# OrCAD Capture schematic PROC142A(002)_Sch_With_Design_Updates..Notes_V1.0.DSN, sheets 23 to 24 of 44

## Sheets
23 22. CPSW RGMII_1 ETHERNET PHY: size C; title: CPSW RGMII_1 ETHERNET PHY
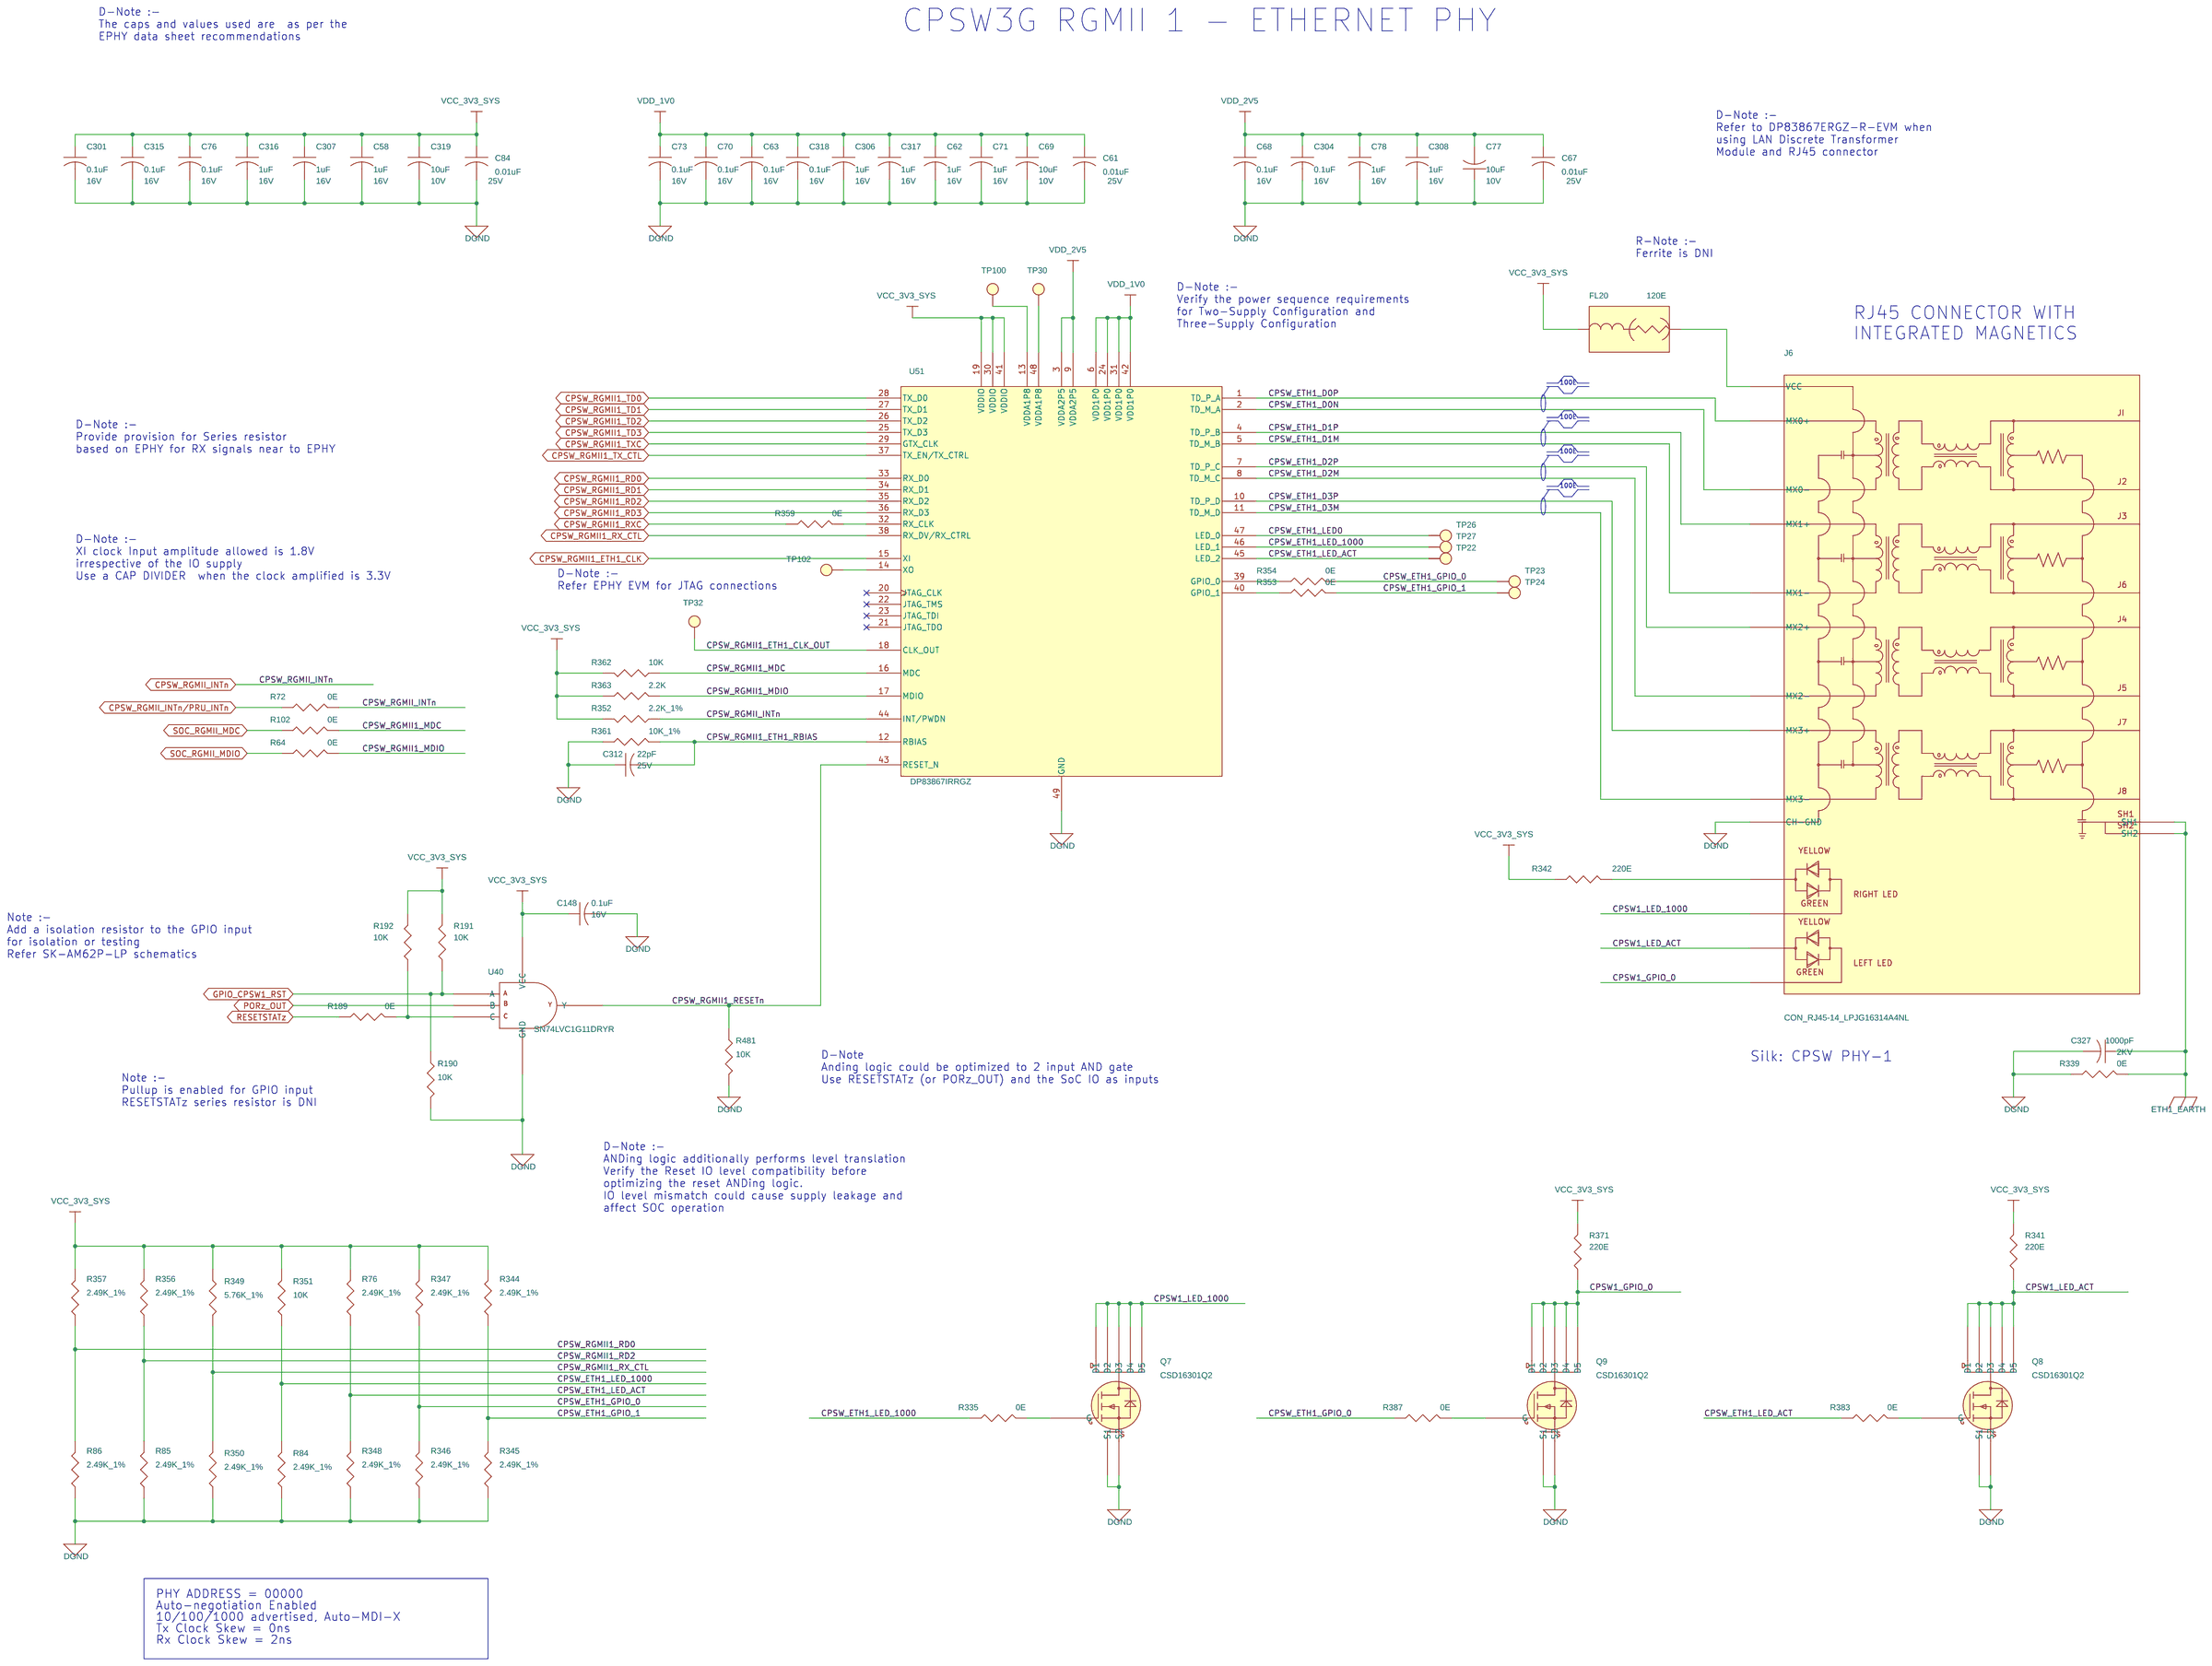
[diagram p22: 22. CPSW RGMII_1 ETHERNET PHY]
24 23. CPSW RGMII_2 ETHERNET PHY: size C; title: CPSW RGMII_2 ETHERNET PHY
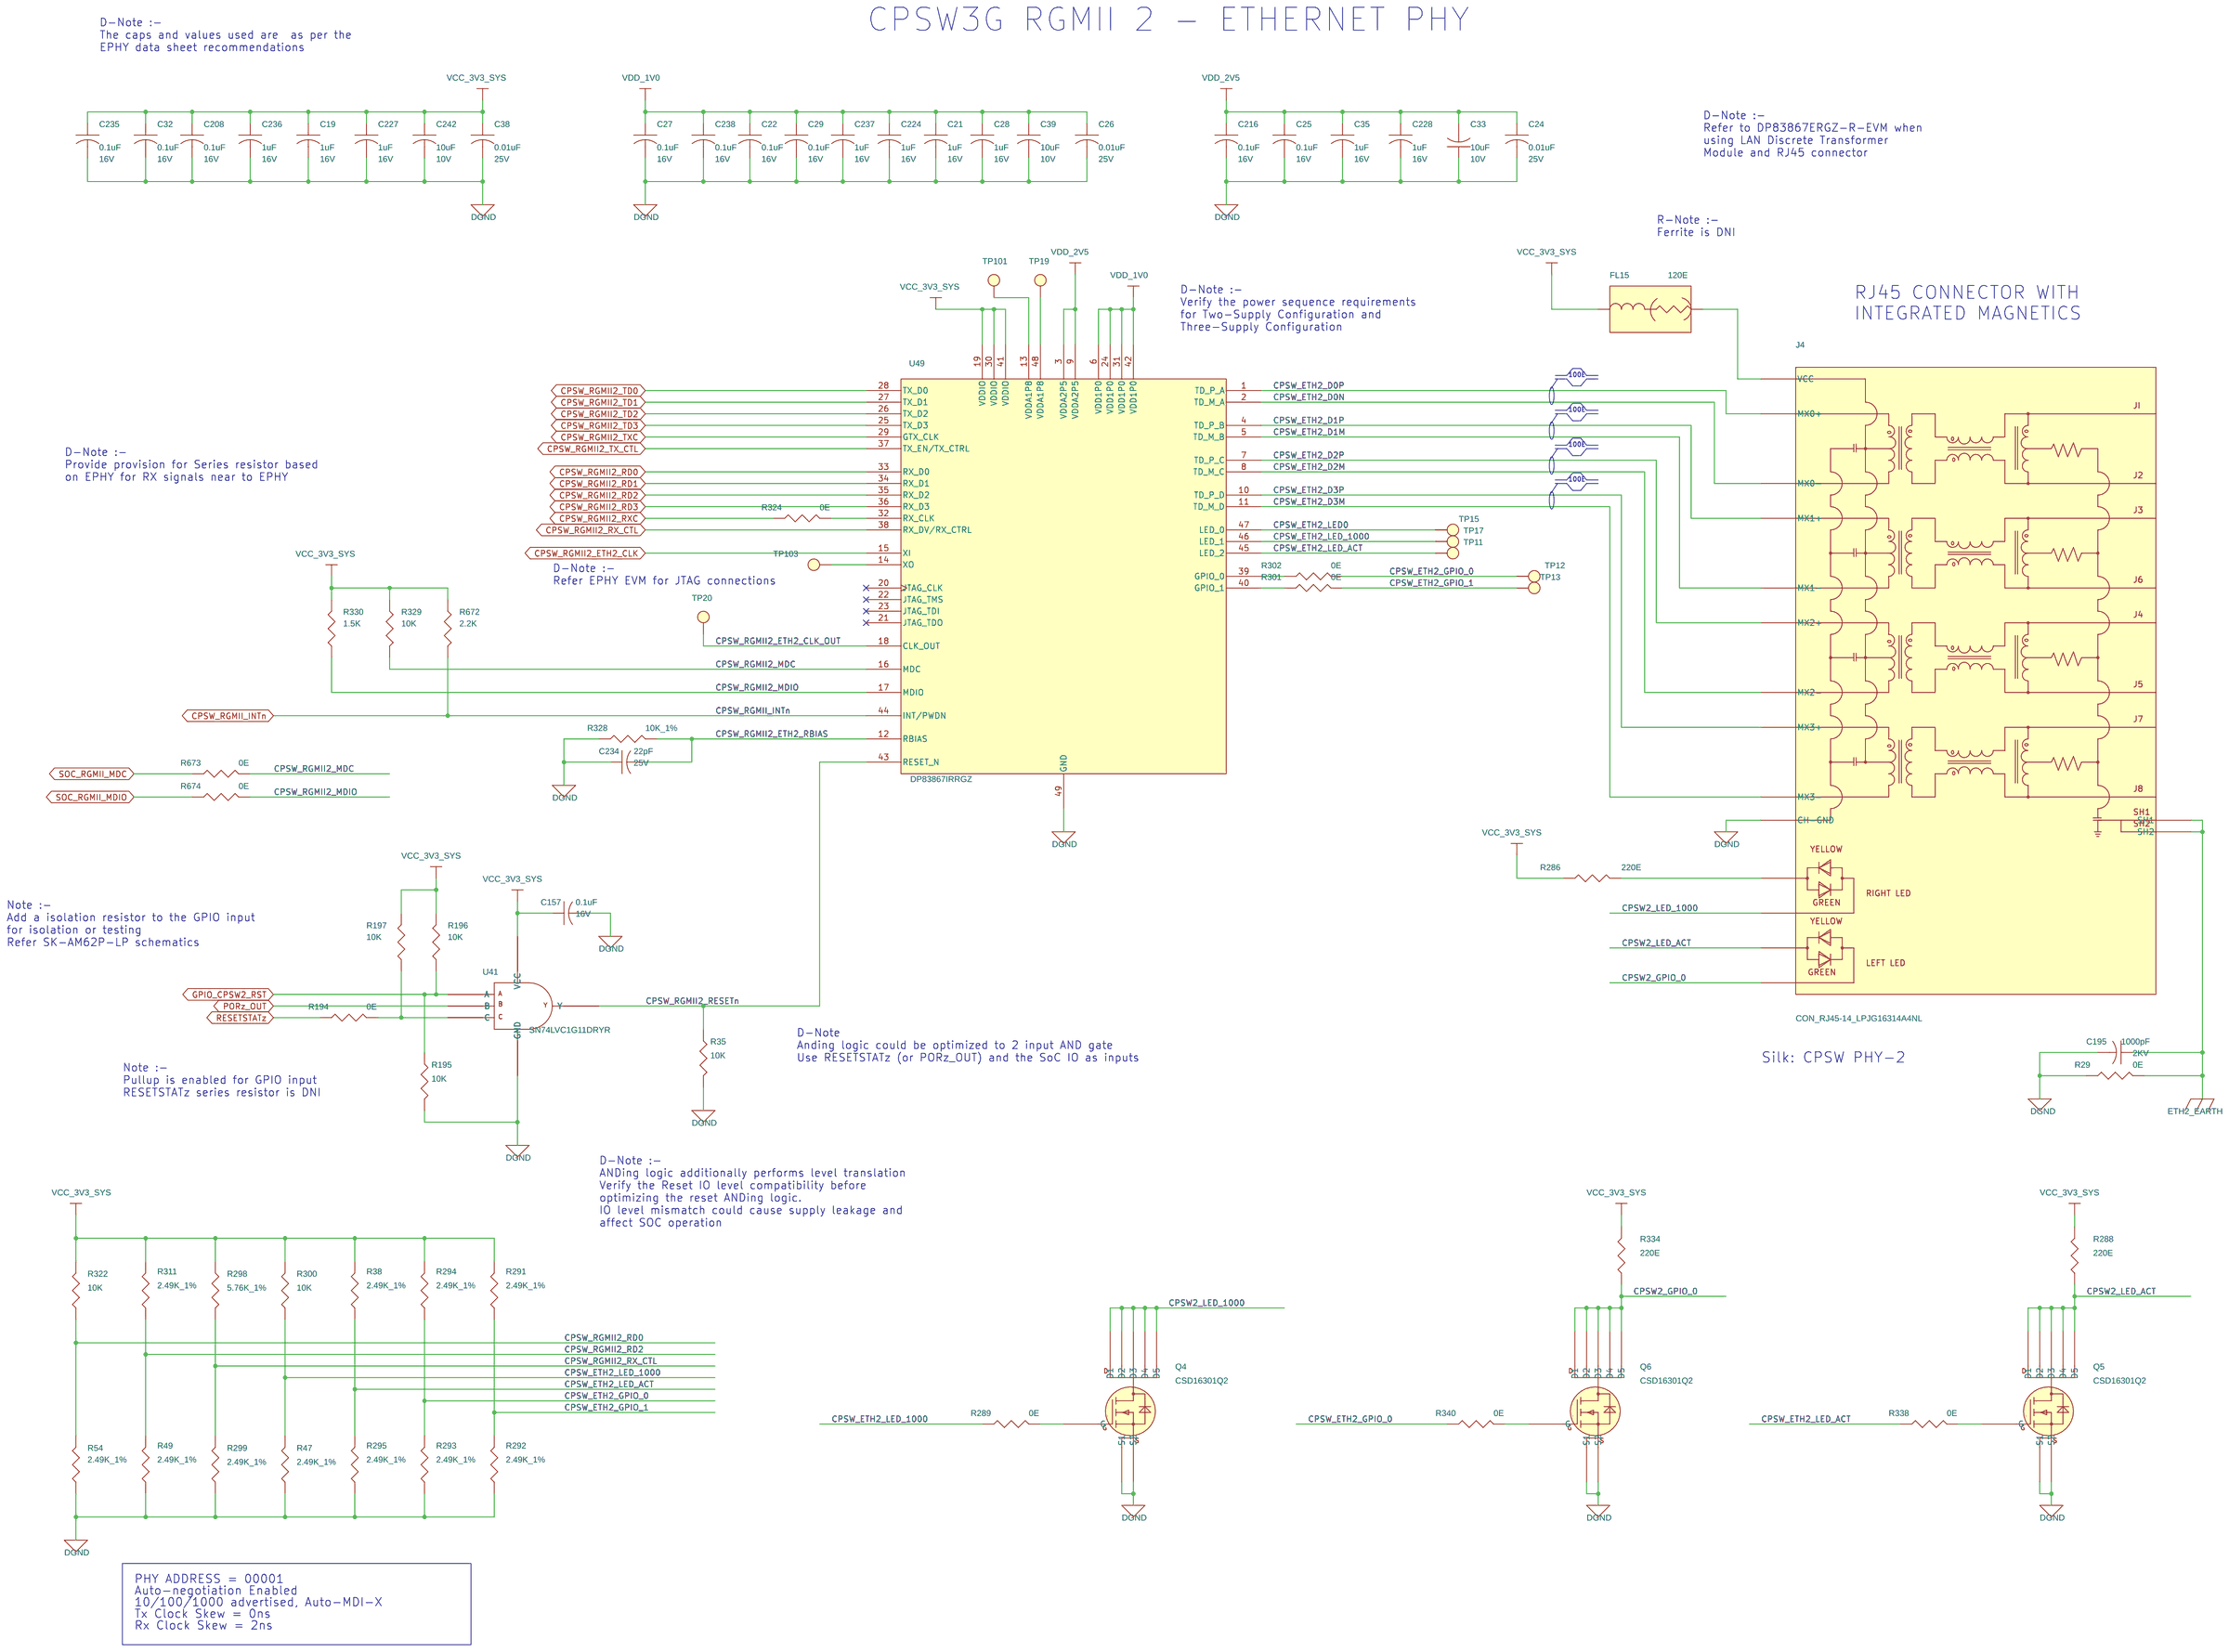
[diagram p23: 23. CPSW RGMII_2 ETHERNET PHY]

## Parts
sheet 22. CPSW RGMII_1 ETHERNET PHY
C58  1uF  [CAP0201_0-5]
C61  0.01uF  [CAP0201_0-5]
C62  1uF  [CAP0201_0-5]
C63  0.1uF  [CAP0201_0-5]
C67  0.01uF  [CAP0201_0-5]
C68  0.1uF  [CAP0201_0-5]
C69  10uF  [CAP0402_0-75]
C70  0.1uF  [CAP0201_0-5]
C71  1uF  [CAP0201_0-5]
C73  0.1uF  [CAP0201_0-5]
C76  0.1uF  [CAP0201_0-5]
C77  10uF  [CAP0402_0-75]
C78  1uF  [CAP0201_0-5]
C84  0.01uF  [CAP0201_0-5]
C148  0.1uF  [CAP0201_0-5]
C301  0.1uF  [CAP0201_0-5]
C304  0.1uF  [CAP0201_0-5]
C306  1uF  [CAP0201_0-5]
C307  1uF  [CAP0201_0-5]
C308  1uF  [CAP0201_0-5]
C312  22pF  [CAP0201_0-5]
C315  0.1uF  [CAP0201_0-5]
C316  1uF  [CAP0201_0-5]
C317  1uF  [CAP0201_0-5]
C318  0.1uF  [CAP0201_0-5]
C319  10uF  [CAP0402_0-75]
C327  1000pF  [CAP1206_1-75]
FL20  120E  [EMIFIL_BLM15P_0402]
J6  CON_RJ45-14_LPJG16314A4NL  [CON_RJ45-14_LPJG16314A4NL_S_R_T_13-6]
Q7  CSD16301Q2  [WSON6_CSD13202Q2_80X80_0-8]
Q8  CSD16301Q2  [WSON6_CSD13202Q2_80X80_0-8]
Q9  CSD16301Q2  [WSON6_CSD13202Q2_80X80_0-8]
R64  0E  [RES0402_0-5]
R72  0E  [RES0402_0-5]
R76  2.49K_1%  [RES0402_0-5]
R84  2.49K_1%  [RES0402_0-5]
R85  2.49K_1%  [RES0402_0-5]
R86  2.49K_1%  [RES0402_0-5]
R102  0E  [RES0402_0-5]
R189  0E  [RES0402_0-5]
R190  10K  [RES0201_0-5]
R191  10K  [RES0201_0-5]
R192  10K  [RES0201_0-5]
R335  0E  [RES0402_0-5]
R339  0E  [RES0603_0-75]
R341  220E  [RES0402_0-5]
R342  220E  [RES0402_0-5]
R344  2.49K_1%  [RES0402_0-5]
R345  2.49K_1%  [RES0402_0-5]
R346  2.49K_1%  [RES0402_0-5]
R347  2.49K_1%  [RES0402_0-5]
R348  2.49K_1%  [RES0402_0-5]
R349  5.76K_1%  [RES0402_0-5]
R350  2.49K_1%  [RES0402_0-5]
R351  10K  [RES0201_0-5]
R352  2.2K_1%  [RES0201_0-5]
R353  0E  [RES0201_0-5]
R354  0E  [RES0201_0-5]
R356  2.49K_1%  [RES0402_0-5]
R357  2.49K_1%  [RES0402_0-5]
R359  0E  [RES0402_0-5]
R361  10K_1%  [RES0201_0-5]
R362  10K  [RES0201_0-5]
R363  2.2K  [RES0201_0-5]
R371  220E  [RES0402_0-5]
R383  0E  [RES0402_0-5]
R387  0E  [RES0402_0-5]
R481  10K  [RES0201_0-5]
TP22  TP20_SMD  [TP20_SMD]
TP23  TP20_SMD  [TP20_SMD]
TP24  TP20_SMD  [TP20_SMD]
TP26  TP20_SMD  [TP20_SMD]
TP27  TP20_SMD  [TP20_SMD]
TP30  TP20_SMD  [TP20_SMD]
TP32  TP20_SMD  [TP20_SMD]
TP100  TP20_SMD  [TP20_SMD]
TP102  TP20_SMD  [TP20_SMD]
U40  SN74LVC1G11DRYR  [SON6_SN74LVC2G17_40X60_0-6]
U51  DP83867IRRGZ  [QFN48_19-68_280X280_1]
sheet 23. CPSW RGMII_2 ETHERNET PHY
C19  1uF  [CAP0201_0-5]
C21  1uF  [CAP0201_0-5]
C22  0.1uF  [CAP0201_0-5]
C24  0.01uF  [CAP0201_0-5]
C25  0.1uF  [CAP0201_0-5]
C26  0.01uF  [CAP0201_0-5]
C27  0.1uF  [CAP0201_0-5]
C28  1uF  [CAP0201_0-5]
C29  0.1uF  [CAP0201_0-5]
C32  0.1uF  [CAP0201_0-5]
C33  10uF  [CAP0402_0-75]
C35  1uF  [CAP0201_0-5]
C38  0.01uF  [CAP0201_0-5]
C39  10uF  [CAP0402_0-75]
C157  0.1uF  [CAP0201_0-5]
C195  1000pF  [CAP1206_1-75]
C208  0.1uF  [CAP0201_0-5]
C216  0.1uF  [CAP0201_0-5]
C224  1uF  [CAP0201_0-5]
C227  1uF  [CAP0201_0-5]
C228  1uF  [CAP0201_0-5]
C234  22pF  [CAP0201_0-5]
C235  0.1uF  [CAP0201_0-5]
C236  1uF  [CAP0201_0-5]
C237  1uF  [CAP0201_0-5]
C238  0.1uF  [CAP0201_0-5]
C242  10uF  [CAP0402_0-75]
FL15  120E  [EMIFIL_BLM15P_0402]
J4  CON_RJ45-14_LPJG16314A4NL  [CON_RJ45-14_LPJG16314A4NL_S_R_T_13-6]
Q4  CSD16301Q2  [WSON6_CSD13202Q2_80X80_0-8]
Q5  CSD16301Q2  [WSON6_CSD13202Q2_80X80_0-8]
Q6  CSD16301Q2  [WSON6_CSD13202Q2_80X80_0-8]
R29  0E  [RES0603_0-75]
R35  10K  [RES0201_0-5]
R38  2.49K_1%  [RES0402_0-5]
R47  2.49K_1%  [RES0402_0-5]
R49  2.49K_1%  [RES0402_0-5]
R54  2.49K_1%  [RES0402_0-5]
R194  0E  [RES0402_0-5]
R195  10K  [RES0201_0-5]
R196  10K  [RES0201_0-5]
R197  10K  [RES0201_0-5]
R286  220E  [RES0402_0-5]
R288  220E  [RES0402_0-5]
R289  0E  [RES0402_0-5]
R291  2.49K_1%  [RES0402_0-5]
R292  2.49K_1%  [RES0402_0-5]
R293  2.49K_1%  [RES0402_0-5]
R294  2.49K_1%  [RES0402_0-5]
R295  2.49K_1%  [RES0402_0-5]
R298  5.76K_1%  [RES0402_0-5]
R299  2.49K_1%  [RES0402_0-5]
R300  10K  [RES0201_0-5]
R301  0E  [RES0201_0-5]
R302  0E  [RES0201_0-5]
R311  2.49K_1%  [RES0402_0-5]
R322  10K  [RES0201_0-5]
R324  0E  [RES0402_0-5]
R328  10K_1%  [RES0201_0-5]
R329  10K  [RES0201_0-5]
R330  1.5K  [RES0201_0-5]
R334  220E  [RES0402_0-5]
R338  0E  [RES0402_0-5]
R340  0E  [RES0402_0-5]
R672  2.2K  [RES0201_0-5]
R673  0E  [RES0402_0-5]
R674  0E  [RES0402_0-5]
TP11  TP20_SMD  [TP20_SMD]
TP12  TP20_SMD  [TP20_SMD]
TP13  TP20_SMD  [TP20_SMD]
TP15  TP20_SMD  [TP20_SMD]
TP17  TP20_SMD  [TP20_SMD]
TP19  TP20_SMD  [TP20_SMD]
TP20  TP20_SMD  [TP20_SMD]
TP101  TP20_SMD  [TP20_SMD]
TP103  TP20_SMD  [TP20_SMD]
U41  SN74LVC1G11DRYR  [SON6_SN74LVC2G17_40X60_0-6]
U49  DP83867IRRGZ  [QFN48_19-68_280X280_1]

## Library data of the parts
C19 C21 C28 C35 C58 C62 C71 C78 C224 C227 C228 C236 C237 C306-C308 C316 C317 = CAP: CAP CERAMIC 1uF 16V 20% X5R 0201; Chkd/date: MANIRAJA/300520; Crtd /date: ALVY/260520; Custom_Duty: 15%; Customs_HS_Code: 85322990; Distributor_name: DIGIKEY; Distributor_part_number: 490-18654-1-ND; Footprint Path: Y:\MIS_DATABASE\Library\ALTIUM_TOOL\PCB_FOOTPRINTS\Altium_Footprint_Lib.PcbLib; Height: 0.39MM; Library Path: Y:\MIS_DATABASE\Library\ALTIUM_TOOL\SCHEMATICS_PARTS\MS_DISCRETE_Library.schlib; Mfr_name: MURATA; Mfr_part_number: GRM033R61C105ME15D; Mistral Part No: 120018090038-R; Package: 0201; Part_type: CAPACITORS\CERAMIC; Project: QCS610_NANOSOM; RoHS: RoHS; Temperature: -55°C+85°C; Tolerance: 20%; Voltage: 16V; Wattage: NA; Weight: 0.33mg; Datasheet: Y:\MIS_DATABASE\DATASHEETS\CAPACITORS\GRM033R61C105ME15.PDF
C24 C26 C38 C61 C67 C84 = CAP: CAP CERAMIC 0.01uF 25V 10% X5R 0201; Chkd/date: MANIRAJA/230118; Crtd /date: MANIRAJA/230118; Custom_Duty: 15%; Customs_HS_Code: 85322990; Distributor_name: DIGIKEY; Distributor_part_number: GRM033R61E103KA12J-ND; Footprint Path: Y:\MIS_DATABASE\Library\ALTIUM_TOOL\PCB_FOOTPRINTS\Altium_Footprint_Lib.PcbLib; Height: 0.33MM; Library Path: Y:\MIS_DATABASE\Library\ALTIUM_TOOL\SCHEMATICS_PARTS\MS_DISCRETE_Library.schlib; Mfr_name: MURATA; Mfr_part_number: GRM033R61E103KA12J; Mistral Part No: 120018010007-R; Package: 0201; Part_type: CAPACITORS\CERAMIC; Project: TI_MAXIE_CPB; RoHS: RoHS; Temperature: -55°C+85°C; Tolerance: 10%; Voltage: 25V; Wattage: NA; Weight: 0.33mg; Datasheet: Y:\MIS_DATABASE\DATASHEETS\CAPACITORS\GRM033R61E103KA12.PDF
C22 C25 C27 C29 C32 C63 C68 C70 C73 C76 C148 C157 C208 C216 C235 C238 C301 C304 C315 C318 = CAP: CAP CERAMIC 0.1uF 16V 10% X5R 0201; Alt_Mfr_name: YAGEO AMERICA; Alt_Mfr_part_number: CC0402KRX5R8BB104; Chkd/date: MANIRAJA/230118; Crtd /date: MANIRAJA/230118; Custom_Duty: 15%; Customs_HS_Code: 85322990; Distributor_name: DIGIKEY; Distributor_part_number: 490-14305-1-ND; Footprint Path: Y:\MIS_DATABASE\Library\ALTIUM_TOOL\PCB_FOOTPRINTS\Altium_Footprint_Lib.PcbLib; Height: 0.33MM; Library Path: Y:\MIS_DATABASE\Library\ALTIUM_TOOL\SCHEMATICS_PARTS\MS_DISCRETE_Library.schlib; Mfr_name: MURATA; Mfr_part_number: GRM033R61C104KE14D; Mistral Part No: 120009030072-R; Package: 0201; Part_type: CAPACITORS\CERAMIC; Project: TI_MAXIE_CPB; RoHS: RoHS; Temperature: -55°C+85°C; Tolerance: 10%; Voltage: 16V; Wattage: NA; Weight: 0.33mg; Datasheet: Y:\MIS_DATABASE\DATASHEETS\CAPACITORS\GRM033R61C104KE14.PDF
C33 C39 C69 C77 C242 C319 = CAP: CAP CERAMIC 10uF 10V 20% X5R 0402; Chkd/date: MANIRAJA/300520; Crtd /date: ALVY/260520; Custom_Duty: 15%; Customs_HS_Code: 85322990; Distributor_name: DIGIKEY; Distributor_part_number: 490-GRM155R61A106ME11DTR-ND; Footprint Path: Y:\MIS_DATABASE\Library\ALTIUM_TOOL\PCB_FOOTPRINTS\Altium_Footprint_Lib.PcbLib; Height: 0.55MM; Library Path: Y:\MIS_DATABASE\Library\ALTIUM_TOOL\SCHEMATICS_PARTS\MS_DISCRETE_Library.schlib; Mfr_name: MURATA; Mfr_part_number: GRM155R61A106ME11D; Mistral Part No: 120013110019-R; Package: 0402; Part_type: CAPACITORS\CERAMIC; Project: QCS610_NANOSOM; RoHS: RoHS; Temperature: -55°C+85°C; Tolerance: 20%; Voltage: 10V; Wattage: NA; Weight: 3.1mg; Datasheet: Y:\MIS_DATABASE\DATASHEETS\CAPACITORS\MURATA-GXX-SER_NOV17.PDF
C234 C312 = CAP: CAP CERAMIC 22pF 25V 1% C0G(NP0) 0201; Chkd/date: MANIRAJA/270721; Crtd /date: ALVY/260721; Custom_Duty: 15%; Customs_HS_Code: 85322990; Distributor_name: DIGIKEY; Distributor_part_number: 490-14545-1-ND; Footprint Path: Y:\MIS_DATABASE\Library\ALTIUM_TOOL\PCB_FOOTPRINTS\Altium_Footprint_Lib.PcbLib; Height: 0.33MM; Library Path: Y:\MIS_DATABASE\Library\ALTIUM_TOOL\SCHEMATICS_PARTS\MS_DISCRETE_Library.schlib; Mfr_name: MURATA; Mfr_part_number: GRM0335C1E220FA01D; Mistral Part No: 120021070019-R; Package: 0201; Part_type: CAPACITORS\CERAMIC; Project: TI_AM335x SK_BRD; RoHS: RoHS; Temperature: -55°C+125°C; Tolerance: 1%; Voltage: 25V; Wattage: NA; Weight: 0.33mg; Datasheet: Y:\MIS_DATABASE\DATASHEETS\CAPACITORS\GRM0335C1E220FA01.PDF
C195 C327 = CAP: CAP CERAMIC 1000pF 2KV 10% X7R 1206; Chkd/date: SHREESHAIL/291106; Crtd /date: MAZHAR/281106; Custom_Duty: 15%; Customs_HS_Code: 85322990; Distributor_name: DIGIKEY; Distributor_part_number: 478-2956-1-ND; Footprint Path: Y:\MIS_DATABASE\Library\ALTIUM_TOOL\PCB_FOOTPRINTS\Altium_Footprint_Lib.PcbLib; Height: 1.52MM; Library Path: Y:\MIS_DATABASE\Library\ALTIUM_TOOL\SCHEMATICS_PARTS\MS_DISCRETE_Library.schlib; Mfr_name: AVX CORPORATION; Mfr_part_number: 1206GC102KAT1A; Mistral Part No: 120015080006-R; Package: 1206; Part_type: CAPACITORS\CERAMIC; Project: ADR1B; RoHS: RoHS; Temperature: -55°C+125°C; Tolerance: 10%; Voltage: 2KV; Wattage: NA; Weight: 16.2mg; Datasheet: Y:\MIS_DATABASE\DATASHEETS\CAPACITORS\AVX_HV-MLC.PDF
FL15 FL20 = EMIFILTER_IND: FERRITE CHIP 120E 2A 0402; Chkd/date: NAVEED/241114; Crtd /date: USMAN/170613; Custom_Duty: 24%; Customs_HS_Code: 85369090; Distributor_name: MOUSER; Distributor_part_number: 81-BLM15PX121SN1D; Height: 0.55MM; Mfr_name: MURATA; Mfr_part_number: BLM15PX121SN1D; Mistral Part No: 130013060022-R; Package: 0402; Part_type: FILTER; Project: GEN_3-8; RoHS: RoHS; Temperature: -55°C+125°C; Tolerance: 25%; Voltage: NA; Wattage: NA; Weight: NA; Datasheet: Y:\MIS_DATABASE\DATASHEETS\DISCRETES\INDUCTORS\BLM15X.PDF
J4 J6 = CON_RJ45-14_LPJG16314A4NL: CON RJ-45 FEMALE 14POS RT TH; Chkd/date: VASANTHA/150714; Crtd /date: BALACHANDAR/120614; Custom_Duty: 24%; Customs_HS_Code: 85369090; Distributor_name: NA; Distributor_part_number: NA; Footprint Path: Y:\MIS_DATABASE\Library\ALTIUM_TOOL\PCB_FOOTPRINTS\Altium_Footprint_Lib.PcbLib; Height: 13.60MM; Library Path: Y:\MIS_DATABASE\Library\ALTIUM_TOOL\SCHEMATICS_PARTS\MS_CONNECTOR_Library.schlib; Mfr_name: LINK-PP; Mfr_part_number: LPJG16314A4NL; Mistral Part No: 150014060029-R; Package: THRU-HOLE; Part_type: CONNECTOR\JACK; Project: AEGIS; RoHS: RoHS; Temperature: -0°C+70°C; Tolerance: NA; Voltage: NA; Wattage: NA; Weight: NA; Datasheet: Y:\MIS_DATABASE\DATASHEETS\CONNECTORS\LPJG16314A4NL.PDF
Q4-Q9 = MOSFET_CSD17313Q2: IC MOSFET N-CHANNEL NEXFET 25V WSON6; Chkd/date: ALVY/071220; Crtd /date: MANIRAJA/071220; Custom_Duty: 15%; Customs_HS_Code: 85423100; Distributor_name: DIGIKEY; Distributor_part_number: 296-25260-1-ND; Footprint Path: Y:\MIS_DATABASE\Library\ALTIUM_TOOL\PCB_FOOTPRINTS\Altium_Footprint_Lib.PcbLib; Height: 0.80MM; Library Path: Y:\MIS_DATABASE\Library\ALTIUM_TOOL\SCHEMATICS_PARTS\MS_MOSFET_Library.schlib; Mfr_name: TEXAS INSTRUMENTS; Mistral Part No: 142020120008-R; Package: WSON6; Part_type: ICS\POWER\MOSFET; Project: TI_AM243x LP EVM; RoHS: RoHS; Temperature: -55°C+150°C; Tolerance: NA; Voltage: NA; Wattage: NA; Weight: 8.7mg; Datasheet: Y:\MIS_DATABASE\DATASHEETS\ICS\POWER\CSD16301Q2.PDF
R64 R72 R102 R189 R194 R289 R335 R338 R340 R383 R387 R673 R674 = RESISTOR: RES 0E 1/16W JUMPER 0402; Chkd/date: VASANTHA/201216; Crtd /date: MUDDU/190810; Custom_Duty: 15%; Customs_HS_Code: 85332119; Distributor_name: DIGIKEY; Distributor_part_number: 541-0.0JCT-ND; Footprint Path: Y:\MIS_DATABASE\Library\ALTIUM_TOOL\PCB_FOOTPRINTS\Altium_Footprint_Lib.PcbLib; Height: 0.40MM; Library Path: Y:\MIS_DATABASE\Library\ALTIUM_TOOL\SCHEMATICS_PARTS\MS_DISCRETE_Library.schlib; Mfr_name: VISHAY; Mfr_part_number: CRCW04020000Z0ED; Mistral Part No: 110010080019-R; Package: 0402; Part_type: RESISTORS\FIXED; Project: PB_BUGBASE; RoHS: RoHS; Temperature: -55°C+155°C; Tolerance: NA; Voltage: NA; Wattage: 1/16W; Weight: 0.65mg; Datasheet: Y:\MIS_DATABASE\DATASHEETS\RESISTORS\CRCW0603.PDF
R38 R47 R49 R54 R76 R84-R86 R291-R295 R299 R311 R344-R348 R350 R356 R357 = RESISTOR: RES 2.49K 1/16W 1% 0402; Chkd/date: VASANTHA/270516; Crtd /date: VASANTHA/270516; Custom_Duty: 15%; Customs_HS_Code: 85332119; Distributor_name: DIGIKEY; Distributor_part_number: 311-2.49KLRCT-ND; Footprint Path: Y:\MIS_DATABASE\Library\ALTIUM_TOOL\PCB_FOOTPRINTS\Altium_Footprint_Lib.PcbLib; Height: 0.40MM; Library Path: Y:\MIS_DATABASE\Library\ALTIUM_TOOL\SCHEMATICS_PARTS\MS_DISCRETE_Library.schlib; Mfr_name: YAGEO AMERICA; Mfr_part_number: RC0402FR-072K49L; Mistral Part No: 110016050020-R; Package: 0402; Part_type: RESISTORS\FIXED; Project: TMDXCSKCC; RoHS: RoHS; Temperature: -55°C+155°C; Tolerance: 1%; Voltage: NA; Wattage: 1/16W; Weight: 0.65mg; Datasheet: Y:\MIS_DATABASE\DATASHEETS\RESISTORS\RCXXXXL-SER_MAR18.PDF
R35 R190-R192 R195-R197 R300 R322 R329 R351 R362 R481 = RESISTOR: RES 10K 1/20W 5% 0201; Chkd/date: MANIRAJA/050517; Crtd /date: MANIRAJA/050517; Custom_Duty: 15%; Customs_HS_Code: 85332119; Distributor_name: DIGIKEY; Distributor_part_number: 311-10KNCT-ND; Footprint Path: Y:\MIS_DATABASE\Library\ALTIUM_TOOL\PCB_FOOTPRINTS\Altium_Footprint_Lib.PcbLib; Height: 0.26MM; Library Path: Y:\MIS_DATABASE\Library\ALTIUM_TOOL\SCHEMATICS_PARTS\MS_DISCRETE_Library.schlib; Mfr_name: YAGEO AMERICA; Mfr_part_number: RC0201JR-0710KL; Mistral Part No: 110010070051-R; Package: 0201; Part_type: RESISTORS\FIXED; Project: GOLDEN-I LITE; RoHS: RoHS; Temperature: -55°C+125°C; Tolerance: 5%; Voltage: NA; Wattage: 1/20W; Weight: 0.17mg; Datasheet: Y:\MIS_DATABASE\DATASHEETS\RESISTORS\RCXXXXL-SER_MAR18.PDF
R29 R339 = RESISTOR: RES 0E 1/10W 5% 0603; Chkd/date: MANIRAJA/051217; Crtd /date: BAVISH/180211; Custom_Duty: 15%; Customs_HS_Code: 85332119; Distributor_name: DIGIKEY; Distributor_part_number: 311-0.0GRCT-ND; Footprint Path: Y:\MIS_DATABASE\Library\ALTIUM_TOOL\PCB_FOOTPRINTS\Altium_Footprint_Lib.PcbLib; Height: 0.55MM; Library Path: Y:\MIS_DATABASE\Library\ALTIUM_TOOL\SCHEMATICS_PARTS\MS_DISCRETE_Library.schlib; Manufacturer: YAGEO AMERICA; Mfr_name: PANASONIC-ECG; Mfr_part_number: RC0603JR-070RL; Mistral Part No: 110011020013-R; Package: 0603; Part_type: RESISTORS\FIXED; Project: KENNEL; RoHS: RoHS; Temperature: -55°C+155°C; Tolerance: 5%; Voltage: NA; Wattage: 1/10W; Weight: 2mg; Datasheet: Y:\MIS_DATABASE\DATASHEETS\RESISTORS\RCXXXXL-SER_MAR18.PDF
R286 R288 R334 R341 R342 R371 = RESISTOR: RES 220E 1/10W 5% 0402; Chkd/date: VASANTHA/291216; Crtd /date: GEETHA/260406; Custom_Duty: 15%; Customs_HS_Code: 85332119; Distributor_name: DIGIKEY; Distributor_part_number: P220JCT-ND; Footprint Path: Y:\MIS_DATABASE\Library\ALTIUM_TOOL\PCB_FOOTPRINTS\Altium_Footprint_Lib.PcbLib; Height: 0.40MM; Library Path: Y:\MIS_DATABASE\Library\ALTIUM_TOOL\SCHEMATICS_PARTS\MS_DISCRETE_Library.schlib; Mfr_name: PANASONIC-ECG; Mfr_part_number: ERJ-2GEJ221X; Mistral Part No: 110009030506-R; Package: 0402; Part_type: RESISTORS\FIXED; Project: RED EYE; RoHS: RoHS; Temperature: -55°C+155°C; Tolerance: 5%; Voltage: NA; Wattage: 1/10W; Weight: 0.8mg; Datasheet: Y:\MIS_DATABASE\DATASHEETS\RESISTORS\PAN-ERJSER_NOV17.PDF
R298 R349 = RESISTOR: RES 5.76K 1/10W 1% 0402; Chkd/date: MAZHAR/150709; Crtd /date: USMAN/220808; Custom_Duty: 15%; Customs_HS_Code: 85332119; Distributor_name: DIGIKEY; Distributor_part_number: P5.76KLCT-ND; Footprint Path: Y:\MIS_DATABASE\Library\ALTIUM_TOOL\PCB_FOOTPRINTS\Altium_Footprint_Lib.PcbLib; Height: 0.40MM; Library Path: Y:\MIS_DATABASE\Library\ALTIUM_TOOL\SCHEMATICS_PARTS\MS_DISCRETE_Library.schlib; Mfr_name: PANASONIC-ECG; Mfr_part_number: ERJ-2RKF5761X; Mistral Part No: 110009030945-R; Package: 0402; Part_type: RESISTORS\FIXED; Project: CPB; RoHS: RoHS; Temperature: -55°C+155°C; Tolerance: 1%; Voltage: NA; Wattage: 1/10W; Weight: 0.8mg; Datasheet: Y:\MIS_DATABASE\DATASHEETS\RESISTORS\PAN-ERJSER_NOV17.PDF
R352 = RESISTOR: RES 2.2K 1/20W 1% 0201; Chkd/date: VASANTHA/270117; Crtd /date: MANIRAJA/270117; Custom_Duty: 15%; Customs_HS_Code: 85332119; Distributor_name: DIGIKEY; Distributor_part_number: YAG2572CT-ND; Footprint Path: Y:\MIS_DATABASE\Library\ALTIUM_TOOL\PCB_FOOTPRINTS\Altium_Footprint_Lib.PcbLib; Height: 0.26MM; Library Path: Y:\MIS_DATABASE\Library\ALTIUM_TOOL\SCHEMATICS_PARTS\MS_DISCRETE_Library.schlib; Manufacturer: YAGEO AMERICA; Mfr_name: PANASONIC-ECG; Mfr_part_number: RC0201FR-072K2L; Mistral Part No: 110017010016-R; Package: 0201; Part_type: RESISTORS\FIXED; Project: GOLDEN-I LITE; RoHS: RoHS; Temperature: -55°C+125°C; Tolerance: 1%; Voltage: NA; Wattage: 1/20W; Weight: 0.17mg; Datasheet: Y:\MIS_DATABASE\DATASHEETS\RESISTORS\RCXXXXL-SER_MAR18.PDF
R301 R302 R353 R354 = RESISTOR: RES 0E 1/20W 5% 0201; Chkd/date: NAVEED/301214; Crtd /date: MUDDU/120710; Custom_Duty: 15%; Customs_HS_Code: 85332119; Distributor_name: DIGIKEY; Distributor_part_number: 311-0.0NCT-ND; Footprint Path: Y:\MIS_DATABASE\Library\ALTIUM_TOOL\PCB_FOOTPRINTS\Altium_Footprint_Lib.PcbLib; Height: 0.26MM; Library Path: Y:\MIS_DATABASE\Library\ALTIUM_TOOL\SCHEMATICS_PARTS\MS_DISCRETE_Library.schlib; Mfr_name: YAGEO AMERICA; Mfr_part_number: RC0201JR-070RL; Mistral Part No: 110010070067-R; Package: 0201; Part_type: RESISTORS\FIXED; Project: PB_BUGBASE; RoHS: RoHS; Temperature: -55°C+125°C; Tolerance: 5%; Voltage: NA; Wattage: 1/20W; Weight: 0.17mg; Datasheet: Y:\MIS_DATABASE\DATASHEETS\RESISTORS\RCXXXXL-SER_MAR18.PDF
R324 R359 = RESISTOR: RES 0E 1/16W JUMPER 0402; Chkd/date: VASANTHA/201216; Crtd /date: MUDDU/190810; Custom_Duty: 15%; Customs_HS_Code: 85332119; Distributor_name: DIGIKEY; Distributor_part_number: 541-0.0JCT-ND; Footprint Path: Y:\MIS_DATABASE\Library\ALTIUM_TOOL\PCB_FOOTPRINTS\Altium_Footprint_Lib.PcbLib; Height: 0.40MM; Library Path: Y:\MIS_DATABASE\Library\ALTIUM_TOOL\SCHEMATICS_PARTS\MS_DISCRETE_Library.schlib; Mfr_name: VISHAY; Mfr_part_number: CRCW04020000Z0ED; Mistral Part No: 110010080019-R; Package: 0402; Part_type: RESISTORS\FIXED; Project: PB_BUGBASE; RoHS: RoHS; SIGNAL_MODEL: RESISTOR_RES0402_0-5_0E_0E; Temperature: -55°C+155°C; Tolerance: NA; Voltage: NA; Wattage: 1/16W; Weight: 0.65mg; Datasheet: Y:\MIS_DATABASE\DATASHEETS\RESISTORS\CRCW0603.PDF
R328 R361 = RESISTOR: RES 10K 1/20W 1% 0201; Chkd/date: VASANTHA/270117; Crtd /date: MANIRAJA/270117; Custom_Duty: 15%; Customs_HS_Code: 85332119; Distributor_name: DIGIKEY; Distributor_part_number: 311-10.0KMCT-ND; Footprint Path: Y:\MIS_DATABASE\Library\ALTIUM_TOOL\PCB_FOOTPRINTS\Altium_Footprint_Lib.PcbLib; Height: 0.26MM; Library Path: Y:\MIS_DATABASE\Library\ALTIUM_TOOL\SCHEMATICS_PARTS\MS_DISCRETE_Library.schlib; Manufacturer: YAGEO AMERICA; Mfr_name: YAGEO AMERICA; Mfr_part_number: RC0201FR-0710KL; Mistral Part No: 110011040018-R; Package: 0201; Part_type: RESISTORS\FIXED; Project: GOLDEN-I LITE; RoHS: RoHS; Temperature: -55°C+125°C; Tolerance: 1%; Voltage: NA; Wattage: 1/20W; Weight: 0.17mg; Datasheet: Y:\MIS_DATABASE\DATASHEETS\RESISTORS\RCXXXXL-SER_MAR18.PDF
R363 R672 = RESISTOR: RES 2.2K 1/20W 5% 0201; Chkd/date: VASANTHA/010117; Crtd /date: MAZHAR/010605; Custom_Duty: 15%; Customs_HS_Code: 85332119; Distributor_name: DIGIKEY; Distributor_part_number: P2.2KAGCT-ND; Footprint Path: Y:\MIS_DATABASE\Library\ALTIUM_TOOL\PCB_FOOTPRINTS\Altium_Footprint_Lib.PcbLib; Height: 0.26MM; Library Path: Y:\MIS_DATABASE\Library\ALTIUM_TOOL\SCHEMATICS_PARTS\MS_DISCRETE_Library.schlib; Mfr_name: PANASONIC-ECG; Mfr_part_number: ERJ-1GEJ222C; Mistral Part No: 110009030427-R; Package: 0201; Part_type: RESISTORS\FIXED; Project: G4SLIM; RoHS: RoHS; Temperature: -55°C+125°C; Tolerance: 5%; Voltage: NA; Wattage: 1/20W; Weight: 0.15mg; Datasheet: Y:\MIS_DATABASE\DATASHEETS\RESISTORS\PAN-ERJXGE-FEB06.PDF
TP11-TP13 TP15 TP17 TP19 TP20 TP22-TP24 TP26 TP27 TP30 TP32 TP100-TP103 = TESTPOINT: TESTPOINT CIR 20 SMD; Chkd/date: SHREESHAIL/171006; Crtd /date: MAZHAR/171006; Custom_Duty: NA; Customs_HS_Code: NA; Distributor_name: NA; Distributor_part_number: NA; Footprint Path: Y:\MIS_DATABASE\Library\ALTIUM_TOOL\PCB_FOOTPRINTS\Altium_Footprint_Lib.PcbLib; Height: NA; Library Path: Y:\MIS_DATABASE\Library\ALTIUM_TOOL\SCHEMATICS_PARTS\MS_DISCRETE_Library.schlib; MECHANICAL 3D STEP FILE: NA; Mfr_name: LOCAL; Mistral Part No: NA; Package: SMD; Project: BT MODULE_CSRBC04; RoHS: NA; Temperature: NA; Tolerance: NA; Voltage: NA; Wattage: NA; Weight: NA; Datasheet: NA
U40 U41 = SN74LVC1G11DCKR_SC70-6: IC SINGLE 3-INPUT POSITIVE-AND GATE SON6; Chkd/date: MANIRAJA/270121; Crtd /date: ALVY/270121; Custom_Duty: 15%; Customs_HS_Code: 85423100; Distributor_name: DIGIKEY; Distributor_part_number: 296-30120-1-ND; Footprint Path: Y:\MIS_DATABASE\Library\ALTIUM_TOOL\PCB_FOOTPRINTS\Altium_Footprint_Lib.PcbLib; Height: 0.60MM; Library Path: Y:\MIS_DATABASE\Library\ALTIUM_TOOL\SCHEMATICS_PARTS\MS_GATE_Library.schlib; Mfr_name: TEXAS INSTRUMENTS; Mistral Part No: 141021010013-R; Package: SON6; Part_type: ICS\DIGITAL\GATES; Project: AM64X_SKEVM; RoHS: RoHS; Temperature: -40°C+125°C; Tolerance: NA; Voltage: NA; Wattage: NA; Weight: 33mg; Datasheet: Y:\MIS_DATABASE\DATASHEETS\ICS\DIGITAL\GATES\SN74LVC1G_NOV16.PDF
U49 U51 = DP83867IRRGZ_VQFN48: IC HIGH IMMUNITY 10/100/1000 Mb/s ETHERNET PHY LAYER TRANSCEIVER VQFN48; Chkd/date: MANIRAJA/110817; Crtd /date: MANIRAJA/110817; Custom_Duty: 15%; Customs_HS_Code: 85423100; Distributor_name: DIGIKEY; Distributor_part_number: DP83867IRRGZT-ND; Height: 1.00MM; Mfr_name: TEXAS INSTRUMENTS; Mistral Part No: 143017080002-R; Package: VQFN48; Part_type: ICS\TELECOM\TRANSCEIVER; Project: TI_SVB_CONTROLLER CARD; RoHS: RoHS; Temperature: -40°C+85°C; Tolerance: NA; Voltage: NA; Wattage: NA; Weight: NA; Datasheet: Y:\MIS_DATABASE\DATASHEETS\ICS\DIGITAL\BUSTRANSCEIVER\DP83867I.PDF
R330 = RESISTOR: RES 1.5K 1/20W 5% 0201; Chkd/date: MAZHAR/130208; Crtd /date: USMAN/130208; Custom_Duty: 15%; Customs_HS_Code: 85332119; Distributor_name: DIGIKEY; Distributor_part_number: P1.5KAGCT-ND; Footprint Path: Y:\MIS_DATABASE\Library\ALTIUM_TOOL\PCB_FOOTPRINTS\Altium_Footprint_Lib.PcbLib; Height: 0.26MM; Library Path: Y:\MIS_DATABASE\Library\ALTIUM_TOOL\SCHEMATICS_PARTS\MS_DISCRETE_Library.schlib; Manufacturer: PANASONIC-ECG; Mfr_name: PANASONIC-ECG; Mfr_part_number: ERJ-1GEJ152C; Mistral Part No: 110010070057-R; Package: 0201; Part_type: RESISTORS\FIXED; Project: SMART VIEW_IP CAMERA; RoHS: RoHS; Temperature: -55°C+125°C; Tolerance: 5%; Voltage: NA; Wattage: 1/20W; Weight: 0.15mg; Datasheet: Y:\MIS_DATABASE\DATASHEETS\RESISTORS\PAN-ERJXGE-FEB06.PDF

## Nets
DGND: C19.2 C21.2 C22.2 C24.2 C25.2 C26.2 C27.2 C28.2 C29.2 C32.2 C33.1 C35.2 C38.2 C39.2 C58.2 C61.2 C62.2 C63.2 C67.2 C68.2 C69.2 C70.2 C71.2 C73.2 C76.2 C77.1 C78.2 C84.2 C148.2 C157.2 C195.2 C208.2 C216.2 C224.2 C227.2 C228.2 C234.1 C235.2 C236.2 C237.2 C238.2 C242.2 C301.2 C304.2 C306.2 C307.2 C308.2 C312.1 C315.2 C316.2 C317.2 C318.2 C319.2 C327.2 J4.1(CH-GND) J6.1(CH-GND) Q4.4(S1) Q4.7(S2) Q5.4(S1) Q5.7(S2) Q6.4(S1) Q6.7(S2) Q7.4(S1) Q7.7(S2) Q8.4(S1) Q8.7(S2) Q9.4(S1) Q9.7(S2) R29.2 R35.2 R47.1 R49.1 R54.1 R84.1 R85.1 R86.1 R190.2 R195.2 R292.1 R293.1 R295.1 R299.1 R328.2 R339.2 R345.1 R346.1 R348.1 R350.1 R361.2 R481.2 U40.2(GND) U41.2(GND) U49.49(GND) U51.49(GND) ; also on sheet 1 10 11 12 13 14 15 16 17 18 19 20 21 22 25 26 27 28 29 30 31 32 33 34 35 36 37 38 39 40 41 42 43
VCC_3V3_SYS: C19.1 C32.1 C38.1 C58.1 C76.1 C84.1 C148.1 C157.1 C208.1 C227.1 C235.1 C236.1 C242.1 C301.1 C307.1 C315.1 C316.1 C319.1 FL15.1 FL20.1 R38.2 R76.2 R191.2 R192.2 R196.2 R197.2 R286.1 R288.2 R291.2 R294.2 R298.1 R300.2 R311.2 R322.2 R329.1 R330.2 R334.2 R341.2 R342.1 R344.2 R347.2 R349.1 R351.2 R352.2 R356.2 R357.2 R362.2 R363.1 R371.2 R672.1 U40.5(VCC) U41.5(VCC) U49.19(VDDIO) U49.30(VDDIO) U49.41(VDDIO) U51.19(VDDIO) U51.30(VDDIO) U51.41(VDDIO) ; also on sheet 10 12 13 14 18 19 20 22 25 26 27 29 30 31 32 33 34 35 36 37 38 39 40 41 42 43
VDD_1V0: C21.1 C22.1 C26.1 C27.1 C28.1 C29.1 C39.1 C61.1 C62.1 C63.1 C69.1 C70.1 C71.1 C73.1 C224.1 C237.1 C238.1 C306.1 C317.1 C318.1 U49.6(VDD1P0) U49.24(VDD1P0) U49.31(VDD1P0) U49.42(VDD1P0) U51.6(VDD1P0) U51.24(VDD1P0) U51.31(VDD1P0) U51.42(VDD1P0) ; also on sheet 12
VDD_2V5: C24.1 C25.1 C33.2 C35.1 C67.1 C68.1 C77.2 C78.1 C216.1 C228.1 C304.1 C308.1 U49.3(VDDA2P5) U49.9(VDDA2P5) U51.3(VDDA2P5) U51.9(VDDA2P5) ; also on sheet 13 17
CPSW1_GPIO_0: J6.14 Q9.1(D1) Q9.2(D2) Q9.5(D3) Q9.6(D4) Q9.8(D5) R371.1
CPSW1_LED_1000: J6.12 Q7.1(D1) Q7.2(D2) Q7.5(D3) Q7.6(D4) Q7.8(D5)
CPSW1_LED_ACT: J6.13 Q8.1(D1) Q8.2(D2) Q8.5(D3) Q8.6(D4) Q8.8(D5) R341.1
CPSW2_GPIO_0: J4.14 Q6.1(D1) Q6.2(D2) Q6.5(D3) Q6.6(D4) Q6.8(D5) R334.1
CPSW2_LED_1000: J4.12 Q4.1(D1) Q4.2(D2) Q4.5(D3) Q4.6(D4) Q4.8(D5)
CPSW2_LED_ACT: J4.13 Q5.1(D1) Q5.2(D2) Q5.5(D3) Q5.6(D4) Q5.8(D5) R288.1
CPSW_ETH1_D0N: J6.10(MX0-) U51.2(TD_M_A)
CPSW_ETH1_D0P: J6.9(MX0+) U51.1(TD_P_A)
CPSW_ETH1_D1M: J6.8(MX1-) U51.5(TD_M_B)
CPSW_ETH1_D1P: J6.7(MX1+) U51.4(TD_P_B)
CPSW_ETH1_D2M: J6.6(MX2-) U51.8(TD_M_C)
CPSW_ETH1_D2P: J6.5(MX2+) U51.7(TD_P_C)
CPSW_ETH1_D3M: J6.4(MX3-) U51.11(TD_M_D)
CPSW_ETH1_D3P: J6.3(MX3+) U51.10(TD_P_D)
CPSW_ETH1_GPIO_0: R346.2 R347.1 R354.1 R387.1 TP23.1(TP)
CPSW_ETH1_GPIO_1: R344.1 R345.2 R353.1 TP24.1(TP)
CPSW_ETH1_LED0: TP26.1(TP) U51.47(LED_0)
CPSW_ETH1_LED_1000: R84.2 R335.1 R351.1 TP27.1(TP) U51.46(LED_1)
CPSW_ETH1_LED_ACT: R76.1 R348.2 R383.1 TP22.1(TP) U51.45(LED_2)
CPSW_ETH2_D0N: J4.10(MX0-) U49.2(TD_M_A)
CPSW_ETH2_D0P: J4.9(MX0+) U49.1(TD_P_A)
CPSW_ETH2_D1M: J4.8(MX1-) U49.5(TD_M_B)
CPSW_ETH2_D1P: J4.7(MX1+) U49.4(TD_P_B)
CPSW_ETH2_D2M: J4.6(MX2-) U49.8(TD_M_C)
CPSW_ETH2_D2P: J4.5(MX2+) U49.7(TD_P_C)
CPSW_ETH2_D3M: J4.4(MX3-) U49.11(TD_M_D)
CPSW_ETH2_D3P: J4.3(MX3+) U49.10(TD_P_D)
CPSW_ETH2_GPIO_0: R293.2 R294.1 R302.1 R340.1 TP12.1(TP)
CPSW_ETH2_GPIO_1: R291.1 R292.2 R301.1 TP13.1(TP)
CPSW_ETH2_LED0: TP15.1(TP) U49.47(LED_0)
CPSW_ETH2_LED_1000: R47.2 R289.1 R300.1 TP17.1(TP) U49.46(LED_1)
CPSW_ETH2_LED_ACT: R38.1 R295.2 R338.1 TP11.1(TP) U49.45(LED_2)
CPSW_RGMII1_ETH1_CLK: U51.15(XI) ; also on sheet 25
CPSW_RGMII1_ETH1_CLK_OUT: TP32.1(TP) U51.18(CLK_OUT)
CPSW_RGMII1_ETH1_RBIAS: C312.2 R361.1 U51.12(RBIAS)
CPSW_RGMII1_MDC: R102.2 R362.1 U51.16(MDC)
CPSW_RGMII1_MDIO: R64.2 R363.2 U51.17(MDIO)
CPSW_RGMII1_RD0: R86.2 R357.1 U51.33(RX_D0) ; also on sheet 25
CPSW_RGMII1_RD1: U51.34(RX_D1) ; also on sheet 25
CPSW_RGMII1_RD2: R85.2 R356.1 U51.35(RX_D2) ; also on sheet 25
CPSW_RGMII1_RD3: U51.36(RX_D3) ; also on sheet 25
CPSW_RGMII1_RESETn: R481.1 U40.4(Y) U51.43(RESET_N)
CPSW_RGMII1_RX_CTL: R349.2 R350.2 U51.38(RX_DV/RX_CTRL) ; also on sheet 25
CPSW_RGMII1_RXC: R359.1 ; also on sheet 25
CPSW_RGMII1_TD0: U51.28(TX_D0) ; also on sheet 25
CPSW_RGMII1_TD1: U51.27(TX_D1) ; also on sheet 25
CPSW_RGMII1_TD2: U51.26(TX_D2) ; also on sheet 25
CPSW_RGMII1_TD3: U51.25(TX_D3) ; also on sheet 25
CPSW_RGMII1_TX_CTL: U51.37(TX_EN/TX_CTRL) ; also on sheet 25
CPSW_RGMII1_TXC: U51.29(GTX_CLK) ; also on sheet 25
CPSW_RGMII2_ETH2_CLK: U49.15(XI) ; also on sheet 25
CPSW_RGMII2_ETH2_CLK_OUT: TP20.1(TP) U49.18(CLK_OUT)
CPSW_RGMII2_ETH2_RBIAS: C234.2 R328.1 U49.12(RBIAS)
CPSW_RGMII2_MDC: R329.2 R673.2 U49.16(MDC)
CPSW_RGMII2_MDIO: R330.1 R674.2 U49.17(MDIO)
CPSW_RGMII2_RD0: R54.2 R322.1 U49.33(RX_D0) ; also on sheet 25
CPSW_RGMII2_RD1: U49.34(RX_D1) ; also on sheet 25
CPSW_RGMII2_RD2: R49.2 R311.1 U49.35(RX_D2) ; also on sheet 25
CPSW_RGMII2_RD3: U49.36(RX_D3) ; also on sheet 25
CPSW_RGMII2_RESETn: R35.1 U41.4(Y) U49.43(RESET_N)
CPSW_RGMII2_RX_CTL: R298.2 R299.2 U49.38(RX_DV/RX_CTRL) ; also on sheet 25
CPSW_RGMII2_RXC: R324.1 ; also on sheet 25
CPSW_RGMII2_TD0: U49.28(TX_D0) ; also on sheet 25
CPSW_RGMII2_TD1: U49.27(TX_D1) ; also on sheet 25
CPSW_RGMII2_TD2: U49.26(TX_D2) ; also on sheet 25
CPSW_RGMII2_TD3: U49.25(TX_D3) ; also on sheet 25
CPSW_RGMII2_TX_CTL: U49.37(TX_EN/TX_CTRL) ; also on sheet 25
CPSW_RGMII2_TXC: U49.29(GTX_CLK) ; also on sheet 25
CPSW_RGMII_INTn: R72.2 R352.1 R672.2 U49.44(INT/PWDN) U51.44(INT/PWDN)
CPSW_RGMII_INTn/PRU_INTn: R72.1 ; also on sheet 32 42
ETH1_EARTH: C327.1 J6.15(SH1) J6.16(SH2) R339.1
ETH2_EARTH: C195.1 J4.15(SH1) J4.16(SH2) R29.1
GPIO_CPSW1_RST: R190.1 R191.1 U40.1(A) ; also on sheet 39
GPIO_CPSW2_RST: R195.1 R196.1 U41.1(A) ; also on sheet 39
PORz_OUT: U40.3(B) U41.3(B) ; also on sheet 20 27 42
RESETSTATz: R189.1 R194.1 ; also on sheet 13 19 20 21 27 32 33 37 39 40 41 42
SOC_RGMII_MDC: R102.1 R673.1 ; also on sheet 32
SOC_RGMII_MDIO: R64.1 R674.1 ; also on sheet 32
N16800246: FL15.2 J4.2(VCC)
N17110597: TP100.1(TP) U51.13(VDDA1P8)
N17133547: FL20.2 J6.2(VCC)
N17137240: J6.11 R342.2
N17149186: TP101.1(TP) U49.13(VDDA1P8)
N17149287: J4.11 R286.2
N17167245: R359.2 U51.32(RX_CLK)
N17167691: R324.2 U49.32(RX_CLK)
N17269599: R189.2 R192.1 U40.6(C)
N17434691: TP19.1(TP) U49.48(VDDA1P8)
N17473283: R194.2 R197.1 U41.6(C)
N17653582: Q7.3(G) R335.2
N17654451: Q4.3(G) R289.2
N17796705: Q8.3(G) R383.2
N17796716: Q9.3(G) R387.2
N17799775: Q6.3(G) R340.2
N17800599: Q5.3(G) R338.2
N18576337: R354.2 U51.39(GPIO_0)
N18576340: R353.2 U51.40(GPIO_1)
N18576730: R302.2 U49.39(GPIO_0)
N18576733: R301.2 U49.40(GPIO_1)
N20273833: TP30.1(TP) U51.48(VDDA1P8)
N20274021: TP102.1(TP) U51.14(XO)
N20274420: TP103.1(TP) U49.14(XO)

Not connected (* = marked no-connect by the designer): U49 20(JTAG_CLK)* 21(JTAG_TDO)* 22(JTAG_TMS)* 23(JTAG_TDI)*; U51 20(JTAG_CLK)* 21(JTAG_TDO)* 22(JTAG_TMS)* 23(JTAG_TDI)*

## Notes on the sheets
sheet 23
- D-Note :-
  The caps and values used are  as per the
  EPHY data sheet recommendations
- CPSW3G RGMII 1 - ETHERNET PHY
- D-Note :-
  Refer to DP83867ERGZ-R-EVM when
  using LAN Discrete Transformer
  Module and RJ45 connector
- R-Note :-
  Ferrite is DNI
- D-Note :-
  Verify the power sequence requirements
  for Two-Supply Configuration and
  Three-Supply Configuration
- RJ45 CONNECTOR WITH
  INTEGRATED MAGNETICS
- 100E
- 100E
- D-Note :-
  Provide provision for Series resistor
  based on EPHY for RX signals near to EPHY
- 100E
- 100E
- D-Note :-
  XI clock Input amplitude allowed is 1.8V
  irrespective of the IO supply
  Use a CAP DIVIDER  when the clock amplified is 3.3V
- D-Note :-
  Refer EPHY EVM for JTAG connections
- Note :-
  Add a isolation resistor to the GPIO input
  for isolation or testing
  Refer SK-AM62P-LP schematics
- D-Note
  Anding logic could be optimized to 2 input AND gate
  Use RESETSTATz (or PORz_OUT) and the SoC IO as inputs
- Silk: CPSW PHY-1
- Note :-
  Pullup is enabled for GPIO input
  RESETSTATz series resistor is DNI
- D-Note :-
  ANDing logic additionally performs level translation
  Verify the Reset IO level compatibility before
  optimizing the reset ANDing logic.
  IO level mismatch could cause supply leakage and
  affect SOC operation
- PHY ADDRESS = 00000
- Auto-negotiation Enabled
- 10/100/1000 advertised, Auto-MDI-X
- Tx Clock Skew = 0ns
- Rx Clock Skew = 2ns
sheet 24
- CPSW3G RGMII 2 - ETHERNET PHY
- D-Note :-
  The caps and values used are  as per the
  EPHY data sheet recommendations
- D-Note :-
  Refer to DP83867ERGZ-R-EVM when
  using LAN Discrete Transformer
  Module and RJ45 connector
- R-Note :-
  Ferrite is DNI
- D-Note :-
  Verify the power sequence requirements
  for Two-Supply Configuration and
  Three-Supply Configuration
- RJ45 CONNECTOR WITH
  INTEGRATED MAGNETICS
- 100E
- 100E
- D-Note :-
  Provide provision for Series resistor based
  on EPHY for RX signals near to EPHY
- 100E
- 100E
- D-Note :-
  Refer EPHY EVM for JTAG connections
- Note :-
  Add a isolation resistor to the GPIO input
  for isolation or testing
  Refer SK-AM62P-LP schematics
- D-Note
  Anding logic could be optimized to 2 input AND gate
  Use RESETSTATz (or PORz_OUT) and the SoC IO as inputs
- Silk: CPSW PHY-2
- Note :-
  Pullup is enabled for GPIO input
  RESETSTATz series resistor is DNI
- D-Note :-
  ANDing logic additionally performs level translation
  Verify the Reset IO level compatibility before
  optimizing the reset ANDing logic.
  IO level mismatch could cause supply leakage and
  affect SOC operation
- PHY ADDRESS = 00001
- Auto-negotiation Enabled
- 10/100/1000 advertised, Auto-MDI-X
- Tx Clock Skew = 0ns
- Rx Clock Skew = 2ns
